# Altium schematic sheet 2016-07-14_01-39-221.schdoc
size 469 x 147 mm; SheetNumber: 1; SheetTotal: 1
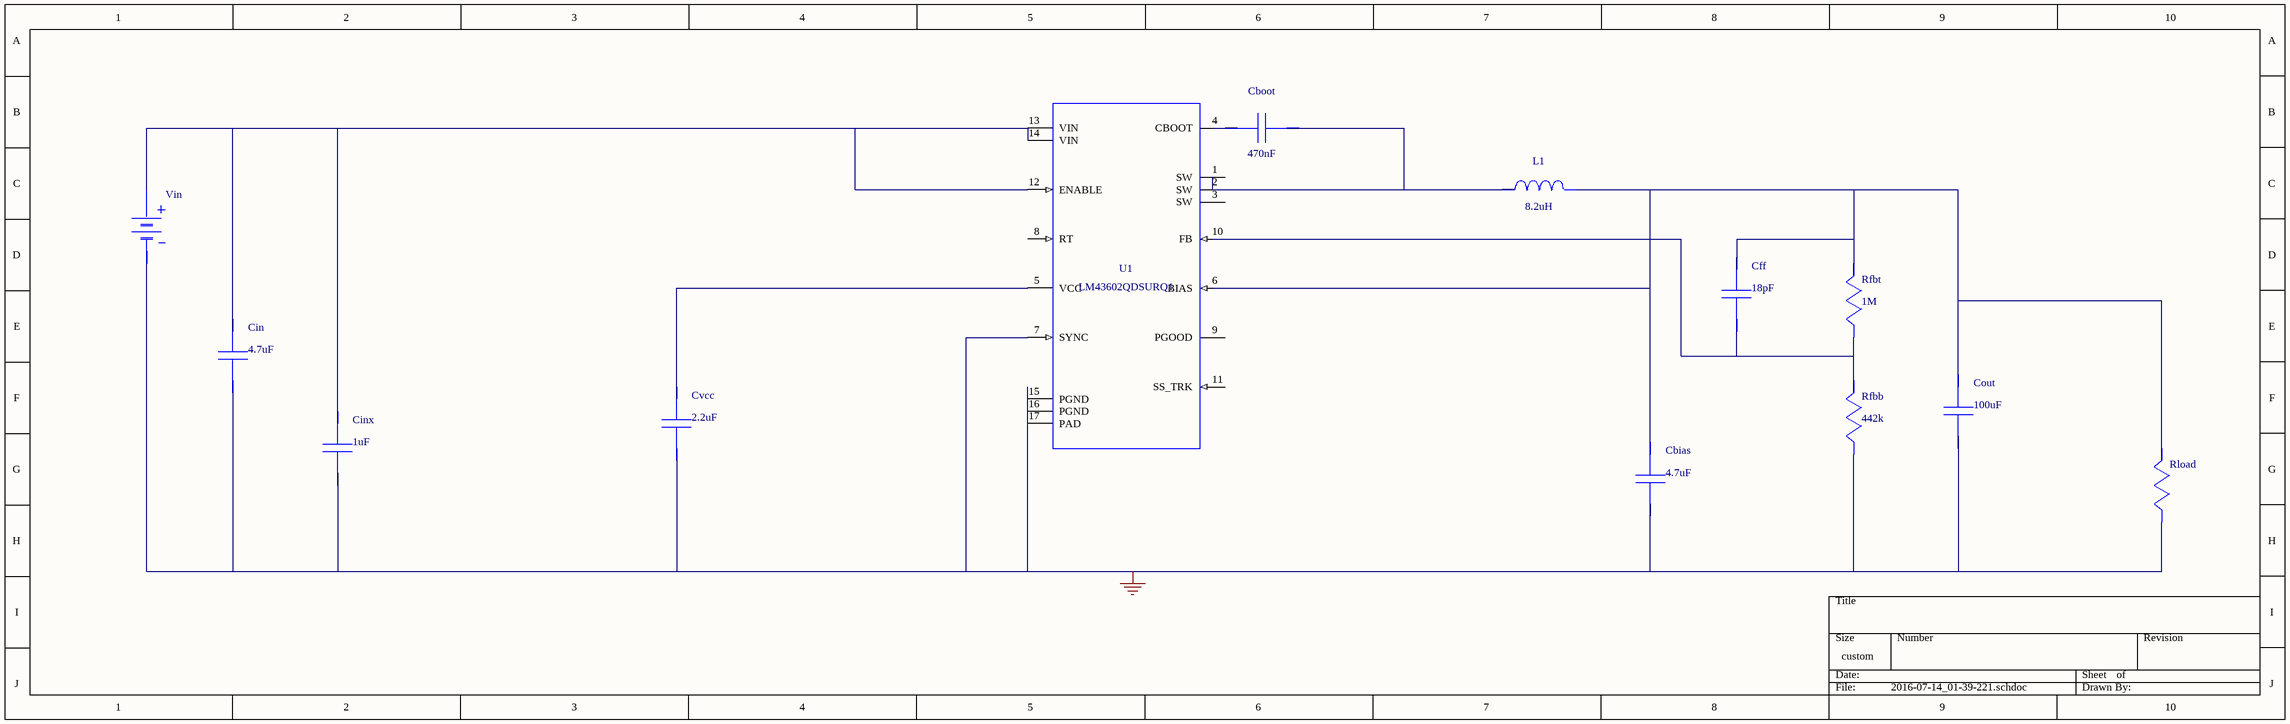
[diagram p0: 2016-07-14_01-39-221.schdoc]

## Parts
Cbias  value 4.7uF  (hidden comment: GRM188R60J475KE19D)
Cboot  value 470nF  (hidden comment: GRM155C80J474KE19D)
Cff  value 18pF  (hidden comment: C0805C180M3GACTU)
Cin  value 4.7uF  (hidden comment: GRM32ER71H475KA88L)
Cinx  value 1uF  (hidden comment: C3216X5R1H105K)
Cout  value 100uF  (hidden comment: GRM31CR60J107ME39L)
Cvcc  value 2.2uF  (hidden comment: GRM155R60J225ME15D)
L1  value 8.2uH  (hidden comment: SRN6045-8R2Y)
Rfbb  value 442k  (hidden comment: CRCW0402442KFKED)
Rfbt  value 1M  (hidden comment: CRCW04021M00FKED)
Rload  WB_LOAD_RESISTOR  (value not drawn)
U1  LM43602QDSURQ1
Vin  WB_BATTERY  (value not drawn)

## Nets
0: Cbias.2 Cin.2 Cinx.2 Cout.2 Cvcc.2 Rfbb.2 Rload.2 U1.7(SYNC) U1.15(PGND) U1.16(PGND) U1.17(PAD) Vin.2(-)
NetCbias_1: Cbias.1 Cff.1 Cout.1 L1.2 Rfbt.1 Rload.1 U1.6(BIAS)
NetCboot_1: Cboot.1 L1.1 U1.2(SW)
NetCboot_2: Cboot.2 U1.4(CBOOT)
NetCff_2: Cff.2 Rfbb.1 Rfbt.2 U1.10(FB)
NetCin_1: Cin.1 Cinx.1 U1.12(ENABLE) U1.13(VIN) U1.14(VIN) Vin.1(+)
NetCvcc_1: Cvcc.1 U1.5(VCC)

Not connected (* = marked no-connect by the designer): U1 1(SW) 3(SW) 8(RT) 9(PGOOD) 11(SS_TRK)

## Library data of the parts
Cbias = GRM188R60J475KE19D: GRM188R60J475KE1; Manufacturer Name: MuRata
Cboot = GRM155C80J474KE19D: GRM155C80J474KE1; Manufacturer Name: MuRata
Cff = C0805C180M3GACTU: Manufacturer Name: Kemet
Cin = GRM32ER71H475KA88L: GRM32ER71H475KA8; Manufacturer Name: MuRata
Cinx = C3216X5R1H105K: Manufacturer Name: TDK
Cout = GRM31CR60J107ME39L: GRM31CR60J107ME3; Manufacturer Name: MuRata
Cvcc = GRM155R60J225ME15D: GRM155R60J225ME1; Manufacturer Name: MuRata
L1 = SRN6045-8R2Y: Manufacturer Name: Bourns
Rfbb = CRCW0402442KFKED: Manufacturer Name: Vishay-Dale
Rfbt = CRCW04021M00FKED: Manufacturer Name: Vishay-Dale
U1 = LM43602QDSURQ1: Manufacturer Name: Texas Instruments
